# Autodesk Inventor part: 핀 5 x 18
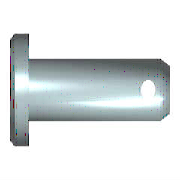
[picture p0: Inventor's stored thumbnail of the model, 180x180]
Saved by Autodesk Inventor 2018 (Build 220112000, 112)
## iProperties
Created: 2012-02
Part Number: 핀 5 x 18
Material: 강철
Description: 머리가 있는 클레비스 핀
Document SubType Name: Modeling
Standard: ISO 2341
Designer: test
Standard Revision: Second edition 1986-11-01
Standards Organization: ISO
Language: ko-KR
Size Designation: B - 5 x 18
Categories: <MemberInstance><Categories><Category DisplayName="조임쇠" InternalName="e4da775c-781d-43d5-af7c-5136215cf5a6" Mnemonic="FSTN"><Category DisplayName="핀" InternalNa
Density: 7.85 g/cm^3
Appearance: 강철
IsCustomPart: 1
Author: test
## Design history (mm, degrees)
sketch "스케치1"
  geometry: L1 (-1.6, 0)-(-1.6, 4); L2 (-1.6, 4)-(0, 4); L3 (0, 4)-(0, 2.5); L4 (0, 2.5)-(18, 2.5); L5 (18, 2.5)-(18, 0); L6 (-1.6, 0)-(18, 0); L7 (-4, 0)-(17, 0) reference; L8 (0, -0.98)-(0, 3.08) reference; C1 r 0.6 at (15.1, 0)
  constraints: 12 end point, 3 parallel, 2 collinear, 2 perpendicular, 1 centre point, 1 point on line, 1 vertical
  dimensions: "d0" = 5 diameter of L4 L6 (= NND); "d1" = 8 diameter of L2 L6 (= KOD); "d2" = 1.6 distance of L1.end L2.end (= KOH); "d3" = 18 distance of L3.end L4.end (= NLG); "d5" = 2.9 distance from line of L5 C1.centre (= DIST); "d6" = 1.2 diameter of C1 (= BOR)
revolve "본체" stored, may be unused: angle "d4" = 90 deg
extrude "구멍" cut sketch "스케치1" extent not by distance; stored distance "d7" = 5 (= NND); taper "d8" = 0 deg
workaxis "Work Axis1"
workplane "Work Plane1"
body "Solid1"
chamfer "모따기1" distance "d9" = 1 (= PHH2); stored, may be unused: angle "d10" = 45 deg (= FAWI2), second distance "d16" = 1 (= PHH2)
chamfer "모따기2" distance "d11" = 2 (= PHH1); stored, may be unused: angle "d12" = 30 deg (= FAWI1), second distance "d17" = 2 (= PHH1)
other parameters: "PHH1" = 2 [user parameter; used in 2 equation terms], "PHH2" = 1 [user parameter; used in 2 equation terms], "KOD" = 8 [user parameter; used in 1 equation term], "KOH" = 1.6 [user parameter; used in 1 equation term], "NND" = 5 [user parameter; used in 2 equation terms], "FAWI1" = 30 deg [user parameter; used in 1 equation term], "FAWI2" = 45 deg [user parameter; used in 1 equation term], "DIST" = 2.9 [user parameter; used in 1 equation term], "BOR" = 1.2 [user parameter; used in 1 equation term], "NLG" = 18 [user parameter; used in 1 equation term], "d13" = 0, "d14" = 0, "d27" = 0, "d28" = 0, "d29" = 0, "d30" = 0, "d31" = 0
